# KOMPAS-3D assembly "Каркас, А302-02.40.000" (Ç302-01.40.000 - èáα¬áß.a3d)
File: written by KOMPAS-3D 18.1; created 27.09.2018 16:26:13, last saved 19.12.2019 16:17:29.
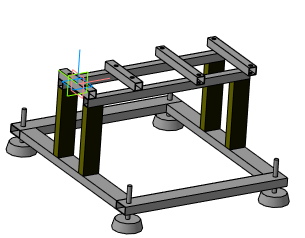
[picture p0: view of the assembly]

Document properties: Автор: Милов; Полное имя файла: D:\Мембранные насосы\Мембранный электропривод\А302-00.00.000 - ASTRA-302 (МЭ200)\3Д ПВХ\А302-01.40.000 - Каркас.a3d

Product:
- Part/product: Каркас  | designation А302-02.40.000  | pos. 0
    Масса: 7.45285
    Раздел спецификации: Сборочные единицы
    Форматы листов документа: 2xA3
    Примечание: @100~)2xA3
    source file: А302-02.00.000 - ASTRA-302 (МЭ200)\А302-02.40.000 - Каркас.cdw
  - Component [detail]: Виброопора PCA-60 M10  | qty 4  | pos. 71  | Масса: 0.60876; Раздел спецификации: Детали; source file: Виброопора PCA-60 M10.m3d
  - Component [detail]: Подставка 2  | designation А302-02.40.003  | qty 2  | pos. 70  | Масса: 0.559738; Раздел спецификации: Детали; source file: А302-02.40.003 - Подставка 2.m3d
  - Component [detail]: Подставка 1  | designation А302-02.40.002  | qty 2  | pos. 38  | Масса: 0.739092; Раздел спецификации: Детали; Форматы листов документа: A4; source file: А302-02.00.000 - ASTRA-302 (МЭ200)\А302-02.40.002 - Подставка.cdw, А302-02.40.002 - Подставка 1.m3d
  - Component [detail]: Опора  | designation А302-02.40.001  | qty 4  | pos. 1  | Масса: 0.291894; Раздел спецификации: Детали; Форматы листов документа: A4; Плотность: 7850; source file: А302-02.00.000 - ASTRA-302 (МЭ200)\А302-02.40.001 - Опора.cdw, Отработка\Труба профильная 25х25х1,5-1.m3d
  - Component [detail]: Сталь 10  ГОСТ 1050-88  | qty 2  | pos. 5  | Масса: 0.109158; Раздел спецификации: Материалы; Примечание: м с учетом  / деталей
- Part/product: Каркас  | designation А302-01.40.000  | pos. 0
    Масса: 3.8215
    Раздел спецификации: Сборочные единицы
    Форматы листов документа: 2xA3
    Примечание: @100~)2xA3
    source file: А302-01.40.000 - Каркас.cdw
  - Component: Заглушка квадратная черная 20х20 мм / арт. 20-20 СЧС  | pos. 4  | Раздел спецификации: Материалы
  - Component [detail]: Труба профильная 20х20х1,5 / Ст3 ГОСТ 380-2005  | qty 2  | pos. 5  | Масса: 0.086802; Раздел спецификации: Материалы; Примечание: м с учетом  / деталей; source file: Отработка\Труба профильная 25х25х1,5.m3d
  - Component [detail]: Труба профильная 20х20х1,5 / Ст3 ГОСТ 380-2005  | qty 2  | pos. 0  | Масса: 0.364568; Раздел спецификации: Материалы; Примечание: м; source file: Отработка\Труба профильная 25х25х1,5.m3d
  - Component [detail]: Труба профильная 20х20х1,5 / Ст3 ГОСТ 380-2005  | qty 4  | pos. 0  | Масса: 0.086802; Раздел спецификации: Материалы; Примечание: м; source file: Отработка\Труба профильная 25х25х1,5.m3d
  - Component [detail]: Опора  | designation А302-01.40.001  | qty 4  | pos. 1  | Масса: 0.186469; Раздел спецификации: Детали; Форматы листов документа: A4; Плотность: 7850; source file: А302-01.40.001 - Опора.cdw, Отработка\Труба профильная 25х25х1,5-1.m3d
  - Component [detail]: Стяжка  | designation А302-01.40.002-01  | qty 2  | pos. 3  | Масса: 0.219609; Раздел спецификации: Детали; Форматы листов документа: A4; source file: Отработка\А302-01.40.002-01 - Стяжка.m3d
  - Component [detail]: Стяжка  | designation А302-01.40.002  | qty 2  | pos. 2  | Масса: 0.107634; Раздел спецификации: Детали; Форматы листов документа: A4; source file: А302-01.40.002 - Стяжка.cdw, Отработка\Труба профильная 25х25х1,5-2.m3d

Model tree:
1. Массив по сетке:1  (2 pattern instances)
     Шаг 1 = 120; Угол раствора = 90
2. Массив по сетке:2  (2 pattern instances)
     Наклон = 180; Шаг 1 = 134; Угол раствора = 90
3. Массив по сетке:4  (2 pattern instances)
     Шаг 1 = 400; Угол раствора = 90
4. Эскиз:1  (with: Операция выдавливания:1)
5. Вырезать элемент выдавливания:1  (with: Операция выдавливания:1)
     Расстояние 1 = 30; Расстояние = -25; Ориентация = 2; Ориентация = 2; Расстояние = -2; Ориентация = 2; Расстояние = -2; Ориентация = 2; Расстояние = 10.5; Расстояние = 60
6. Эскиз:2  (with: Вырезать элемент выдавливания:1)
7. Массив по сетке:5  (with: Операция выдавливания:1)  (2 pattern instances)
     Шаг 1 = 380; Угол раствора = 90
8. Массив по сетке:6  (with: Элемент выдавливания:1)  (2 pattern instances)
     Шаг 1 = 460; Угол раствора = 90
9. Эскиз:3  (with: Элемент выдавливания:1)
10. Элемент выдавливания:1
     Расстояние 2 = 20
11. Массив по сетке:7  (with: Элемент выдавливания:1, Операция выдавливания:1, Вырезать элемент выдавливания:1)  (4 pattern instances)
     Шаг 1 = 380; Угол раствора = 90; Шаг 2 = 460; Расстояние = -25; Ориентация = 2; Ориентация = 2

Expressions: 130.0+50; 358.0+7
Referenced files in D:\Мембранные насосы\Мембранный электропривод\А302-00.00.000 - ASTRA-302 (МЭ200)\3Д ПВХ\Отработка\: Труба профильная 25х25х1,5.m3d, Труба профильная 25х25х1,5-1.m3d, А302-01.40.002-01 - Стяжка.m3d, Труба профильная 25х25х1,5-2.m3d
Referenced files in D:\Мембранные насосы\Мембранный электропривод\А302-00.00.000 - ASTRA-302 (МЭ200)\3Д ПВХ\: А302-01.40.001 - Опора.cdw, А302-01.40.002 - Стяжка.cdw, А302-02.40.002 - Подставка 1.m3d, А302-02.40.003 - Подставка 2.m3d, Виброопора PCA-60 M10.m3d, А302-01.40.000 - Каркас.cdw
Referenced files in D:\Мембранные насосы\Мембранный электропривод\А302-00.00.000 - ASTRA-302 (МЭ200)\3Д ПВХ\А302-02.00.000 - ASTRA-302 (МЭ200)\: А302-02.40.001 - Опора.cdw, А302-02.40.002 - Подставка.cdw
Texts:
  Заглушка квадратная черная 20х20 мм
  арт. 20-20 СЧС
  3D_Doc-graphic.lyt,1.000000-4294967295-279442559910
  м с учетом деталей
  Труба профильная 20х20х1,5
  Ст3 ГОСТ 380-2005
  Труба профильная 25х25х1,5
  м с учетом
  м с учетом  / деталей
  @100~)2xA3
